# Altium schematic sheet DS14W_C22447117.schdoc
size 127 x 101 mm
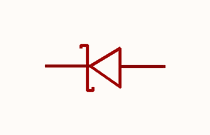
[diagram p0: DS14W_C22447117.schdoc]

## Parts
D?  ds14w_c22447117  [SOD-123FL_L2.7-W1.8-LS3.8-RD]  (value not drawn)

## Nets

Not connected (* = marked no-connect by the designer): D? 1(C) 2(A)

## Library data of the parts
D? = ds14w_c22447117: 二极管配置:独立式;正向压降(Vf):550mV@1A;直流反向耐压(Vr):40V;整流电流:1A;; Manufacturer: JSMSEMI(杰盛微); ManufacturerPart: DS14W; AddInBom: yes; ModelId: 86f9151e155e4fe2af0c4f2e0a80302e; ModelName: SOD-123FL_L2.8-W1.8-H1.1-LS3.6; ModelTransform: 141.732,70.866,0,180,0,0,0,0,0; Diode Configuration: 独立式; Voltage - DC Reverse(Vr): 40V; Current - Rectified: 1A; Reverse Leakage Current (Ir): 300uA@40V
